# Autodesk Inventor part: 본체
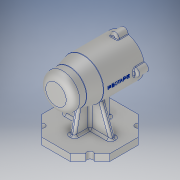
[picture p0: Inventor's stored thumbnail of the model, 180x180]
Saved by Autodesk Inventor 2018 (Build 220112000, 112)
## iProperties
Created: 2021-01
Part Number: 본체
Material: 알루미늄 6061
Document SubType Name: Modeling
Designer: home
Density: 2.7 g/cm^3
Appearance: 알루미늄 - 평지
Mass: 629.962 g
Surface Area: 613.777 cm^2
Volume: 233.319 cm^3
Author: home
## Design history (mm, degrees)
sketch "스케치1"
  geometry: L1 (0, 0)-(30, 0); L2 (30, 0)-(30, 60); L3 (30, 60)-(0, 60); L4 (0, 60)-(0, 0); L5 (30, 60)-(25, 80); L6 (25, 80)-(0, 80); L7 (0, 80)-(0, 60); L8 (0, 80)-(25, 80); L9 (25, 80)-(25, 100); L10 (25, 100)-(0, 100); L11 (0, 100)-(0, 80)
  constraints: 22 end point, 4 parallel, 3 horizontal, 3 perpendicular
  dimensions: "d5" = 30 distance of L1.start L1.end; "d6" = 60 distance of L1.end L2.end; "d9" = 20 distance of L8.end L9.end; "d10" = 25 distance of L9.end L10.end; "d11" = 100 distance between parallel lines of L1 L10
revolve "회전1" sketch "스케치1" stored, may be unused: angle "d12" = 90 deg
node "작업 평면1"
sketch "스케치2"
  geometry: L1 (0, 0)-(-21, 0); L2 (-21, 0)-(-21, 15); L3 (-21, 15)-(0, 15); L4 (0, 15)-(0, 0); L5 (0, 15)-(-24, 15); L6 (-24, 15)-(-24, 57); L7 (-24, 57)-(0, 57); L8 (0, 57)-(0, 15); L9 (0, 57)-(-21, 57); L10 (-21, 57)-(-21, 69); L11 (-21, 69)-(0, 69); L12 (0, 69)-(0, 57); L13 (0, 69)-(-17.5, 69); L14 (-17.5, 69)-(-17.5, 87); L15 (-17.5, 87)-(0, 87); L16 (0, 87)-(0, 69); L17 (0, 87)-(-16, 87); L18 (-16, 87)-(-16, 91); L19 (-16, 91)-(0, 91); L20 (0, 91)-(0, 87); L21 (0, 91)-(-10.5, 91); L22 (-10.5, 91)-(-10.5, 94); L23 (-10.5, 94)-(0, 94); L24 (0, 94)-(0, 91)
  constraints: 48 end point, 12 parallel, 6 horizontal, 6 perpendicular
  dimensions: "d14" = 15 distance of L1.end L2.end; "d15" = 21 distance of L1.start L1.end; "d16" = 42 distance of L5.end L6.end; "d17" = 24 distance of L6.end L7.end; "d18" = 12 distance of L9.end L10.end; "d19" = 21 distance of L10.end L11.end; "d20" = 18 distance of L13.end L14.end; "d21" = 17.5 distance of L14.end L15.end; "d22" = 4 distance of L17.end L18.end; "d23" = 16 distance of L18.end L19.end; "d24" = 3 distance of L21.end L22.end; "d25" = 10.5 distance of L22.end L23.end
revolve "회전2" sketch "스케치2" stored, may be unused: angle "d26" = 90 deg
chamfer "모따기1" distance "d27" = 1; stored, may be unused: second distance "d28" = 2, angle "d29" = 45 deg
fillet "모깎기1" dims "d30" = 3
fillet "모깎기2" dims "d31" = 0.3
sketch "스케치3"
  geometry: C1 r 6 at (0, -30); C2 r 6 at (30, 0); C3 r 6 at (0, 30); C4 r 6 at (-30, 0); 2 further points
  constraints: 4 centre point, 1 vertical alignment, 10 other
  dimensions: "d32" = 12 diameter of C1; "d35" = 360 deg dimension on point (0, 0) C1.centre (derived)
extrude "돌출1" join sketch "스케치3" distance "d37" = 16; taper "d38" = 0 deg
sketch "스케치4" dims "d39" = 60
  geometry: C1 r 7.5 at (0, 30) reference; 6 further points
  constraints: 1 coincident, 1 vertical alignment, 7 other
  dimensions: "d42" = 360 deg dimension on point (0, 30) point (0, 0) (derived)
hole "구멍1" sketch "스케치4" at (0, 0), (30, 30), (0, 60), (-30, 30) diameter "d44" = 3.242; stored, may be unused: countersink angle "d48" = 90 deg, drill point angle "d50" = 118 deg; dims "d45" = 8, "d46" = 4, "d47" = 2, "d49" = 10
node "작업 평면2"
sketch "스케치7"
  geometry: L1 (-20.709, 0)-(-49.998, 29.289); L2 (-49.998, 29.289)-(-49.998, 70.711); L3 (-49.998, 70.711)-(-20.709, 100); L4 (-20.709, 100)-(20.712, 100); L5 (20.712, 100)-(50.002, 70.711); L6 (50.002, 70.711)-(50.002, 29.289); L7 (50.002, 29.289)-(20.712, 0); L8 (20.712, 0)-(-20.709, 0); L9 (0, 0)-(-28.183, 0); L10 (0, 0)-(26.712, 0); 1 further point
  constraints: 20 end point, 2 horizontal, 1 collinear, 17 other
  dimensions: "d62" = 100 distance between parallel lines of L6 L2
extrude "돌출2" join sketch "스케치7" distance "d64" = 10; taper "d65" = 0 deg
sketch "스케치8"
  geometry: L1 (49.998, 70.711)-(20.709, 100) reference; L2 (20.709, 0)-(49.998, 29.289) reference; L3 (-50.002, 29.289)-(-20.712, 0) reference; L4 (-20.712, 100)-(-50.002, 70.711) reference; C1 r 4.5 at (35.354, 85.355); C2 r 4.5 at (35.354, 14.645); C3 r 4.5 at (-35.357, 14.645); C4 r 4.5 at (-35.357, 85.355); 1 further point
  constraints: 4 centre point, 4 midpoint
  dimensions: "d66" = 9 diameter of C1; "d67" = 9 diameter of C2; "d68" = 9 diameter of C3; "d69" = 9 diameter of C4
extrude "돌출3" cut sketch "스케치8" extent not by distance; stored distance "d70" = 10; taper "d71" = 0 deg
node "작업 평면3"
fillet "모깎기3" dims "d93" = 3
sketch "스케치12"
  geometry: L1 (3.998, 77)-(-4.002, 77); L2 (-4.002, 77)-(-4.002, 23); L3 (-4.002, 23)-(3.998, 23); L4 (3.998, 23)-(3.998, 77); L5 (-50.002, 70.711)-(-50.002, 29.289) reference; L6 (-20.712, 0)-(20.709, 0) reference; L7 (20.709, 100)-(-20.712, 100) reference; L8 (3.998, 50)-(-4.002, 50); 1 further point
  constraints: 10 end point, 2 midpoint, 2 parallel, 1 horizontal, 1 perpendicular
  dimensions: "d94" = 8 distance of L2.end L3.end; "d95" = 46 distance between parallel lines of L5 L2; "d97" = 23 distance between parallel lines of L6 L3; "d98" = 23 distance between parallel lines of L7 L1
extrude "돌출5" join sketch "스케치12" stored distance "d99" = 10; taper "d100" = 0 deg
node "작업 평면4"
sketch "스케치13"
  geometry: L1 (65, 100)-(65, 88.537) reference; L2 (75, 100)-(65, 100) reference; L3 (65, 77)-(23.85, 69.001); 1 further point
  constraints: 2 end point
  dimensions: "d104" = 101 deg angle of L3 L1
feature "리브3" sketch "스케치13" dims "d106" = 30, "d107" = 8, "d108" = 0, "d109" = 0, "d110" = 1, "d111" = 1
node "작업 평면5"
sketch "스케치14"
  geometry: L1 (-20.712, 65)-(-32.175, 65) reference; L2 (-35.002, 65)-(-18.69, 20.184); L3 (-50.002, 65)-(-38.539, 65) reference; L4 (-50.002, 75)-(-50.002, 65) reference; L5 (38.536, 65)-(49.998, 65) reference; L6 (49.998, 75)-(49.998, 65) reference; L7 (20.709, 65)-(32.172, 65) reference; 1 further point
  constraints: 2 end point, 1 point on line
  dimensions: "d113" = 110 deg angle of L2 L3
feature "리브4" sketch "스케치14" dims "d119" = 30, "d120" = 8, "d121" = 0, "d122" = 0, "d123" = 1, "d124" = 1
sketch "스케치15"
  geometry: L1 (38.536, 65)-(30.854, 65) reference; L2 (34.998, 65)-(18.479, 19.614); L3 (34.998, 65)-(34.998, 56.091); L4 (49.998, 75)-(49.998, 65) reference; L5 (38.536, 65)-(49.998, 65) reference; 2 further points
  constraints: 4 end point, 1 point on line, 1 vertical
  dimensions: "d125" = 15 distance between parallel lines of L4 L3; "d126" = 110 deg angle of L5 L2
feature "리브5" sketch "스케치15" dims "d127" = 30, "d128" = 8, "d129" = 0, "d130" = 0, "d131" = 1, "d132" = 1
fillet "모깎기4" dims "d133" = 3
fillet "모깎기5" dims "d134" = 3
fillet "모깎기6" dims "d135" = 3
fillet "모깎기7" dims "d136" = 1
fillet "모깎기8" dims "d137" = 10
fillet "모깎기9" dims "d138" = 3
node "작업 평면6"
sketch "스케치16"
  geometry: L1 (-29.226, 0)-(-6.771, 0) reference; 2 further points
  constraints: 1 other
  dimensions: "d140" = 38 distance from line of L1 point (0, 38); "d141" = 0 horizontal distance of point (0, 0) point (0, 38)
feature "엠보싱1" sketch "스케치16" dims "d5" = 30, "d6" = 60, "d9" = 20, "d10" = 25, "d11" = 100, "d142" = 0.5, "d143" = 0
node "솔리드1"
other parameters: "d13" = 0, "d51" = 75, "d101" = 0, "d139" = -58.75
